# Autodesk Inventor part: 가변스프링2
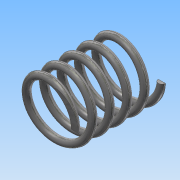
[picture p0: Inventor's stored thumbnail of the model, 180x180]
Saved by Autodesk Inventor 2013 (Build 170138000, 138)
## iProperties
Created: 2018-10
Part Number: 가변스프링2
Material: 스테인리스강
Document SubType Name: Modeling
Designer: Administrator
Density: 8.08 g/cm^3
Mass: 6.269 g
Surface Area: 15.7689 cm^2
Volume: 0.775866 cm^3
Author: Administrator
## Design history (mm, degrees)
sketch "스케치1"
  geometry: L1 (0, 0)-(0, 24.507); L2 (0, 0)-(8, 0); L3 (0, 24.507)-(8, 24.507); C1 r 1 at (8, 0); 1 further point
  constraints: 6 end point, 2 coincident, 1 centre point, 1 parallel, 1 perpendicular, 1 vertical
  dimensions: "d0" = 24.50701 distance of L1.start L1.end (derived); "d1" = 8 distance of L1.start L2.end; "d2" = 2 diameter of C1; "d3" = 8 distance of L1.end L3.end
feature "코일1" sketch "스케치1" pitch "d4" = 10; turns "d6" = 5; dims "d5" = 24.50701 (= d0), "d7" = 0, angle "d8" = 90 deg, angle "d9" = 90 deg, "d10" = 0, "d11" = 0
sketch "스케치2"
  geometry: L1 (0, -10)-(24.507, -10); L2 (24.507, -10)-(24.507, 10); L3 (24.507, 10)-(0, 10); L4 (0, 10)-(0, -10); 2 further points
  constraints: 8 end point, 2 parallel, 1 coincident, 1 horizontal, 1 midpoint, 1 perpendicular
  dimensions: "d12" = 20 distance of L3.end L1.start; "d14" = 24.50701 distance of L1.start L1.end (derived)
extrude "돌출1" sketch "스케치2" stored distance "d15" = 0; taper "d16" = 0 deg
node "솔리드1"
